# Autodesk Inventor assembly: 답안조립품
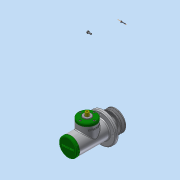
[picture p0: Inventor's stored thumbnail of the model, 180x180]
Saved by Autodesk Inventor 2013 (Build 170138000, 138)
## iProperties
Created: 2016-08
Part Number: 답안조립품
Document SubType Name: Assembly
Designer: dgall
Author: dgall
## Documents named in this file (25)
- C:\Users\dgall\Desktop\460807V1029\답안조립품.iam
- C:\Users\dgall\Desktop\460807V1029\본체.ipt
- C:\Users\dgall\Desktop\460807V1029\공용부품\V-벨트풀리.ipt
- C:\Users\dgall\Desktop\460807V1029\공용부품\너트 M10.ipt
- C:\Users\dgall\Desktop\460807V1029\공용부품\링크.ipt
- C:\Users\dgall\Desktop\460807V1029\공용부품\멈춤링 15 x 1.ipt
- C:\Users\dgall\Desktop\460807V1029\공용부품\멈춤링 35x1.6.ipt
- C:\Users\dgall\Desktop\460807V1029\공용부품\베어링 15 x 35 x 11.ipt
- C:\Users\dgall\Desktop\460807V1029\공용부품\볼트 M4 x 10.ipt
- C:\Users\dgall\Desktop\460807V1029\공용부품\볼트 M4 x 12.ipt
- C:\Users\dgall\Desktop\460807V1029\공용부품\부시1.ipt
- C:\Users\dgall\Desktop\460807V1029\공용부품\부시2.ipt
- C:\Users\dgall\Desktop\460807V1029\공용부품\분할핀 1.6 x 12.ipt
- C:\Users\dgall\Desktop\460807V1029\공용부품\사이드 커버.ipt
- 사이드 커버.ipt
- C:\Users\dgall\Desktop\460807V1029\공용부품\슬라이더.ipt
- C:\Users\dgall\Desktop\460807V1029\공용부품\오일 실 15 25 7.ipt
- C:\Users\dgall\Desktop\460807V1029\공용부품\와셔 4x16.ipt
- C:\Users\dgall\Desktop\460807V1029\공용부품\와셔 10x21.ipt
- C:\Users\dgall\Desktop\460807V1029\공용부품\클래스터 핀 6 x 24.ipt
- C:\Users\dgall\Desktop\460807V1029\공용부품\키 4 x 4 x 18.ipt
- C:\Users\dgall\Desktop\460807V1029\공용부품\탑 부시.ipt
- C:\Users\dgall\Desktop\460807V1029\공용부품\탑 커버.ipt
- 탑 커버.ipt
- C:\Users\dgall\Desktop\460807V1029\공용부품\편심축.ipt
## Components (6 placed, 3 different names)
1. V-벨트풀리:1
2. ISO 4017 M4 x 10:1
3. ISO 4762 M4 x 12:1
4. ISO 4762 M4 x 12:2
5. ISO 4762 M4 x 12:3
6. ISO 4762 M4 x 12:4
